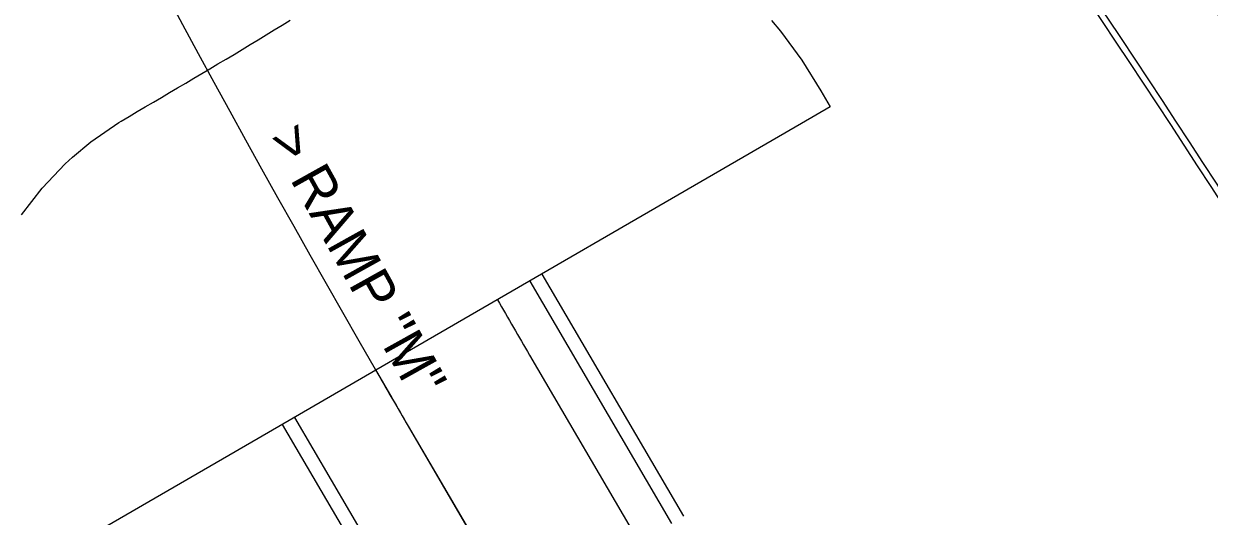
# Model space of a CAD drawing. Extents: x 2145147 to 2158018, y 137519 to 148068.
# Drawn here: x 2150446.2 to 2150572.7, y 142292.5 to 142345 of the extents above; entities that cross this region are included whole.
import ezdxf

# ---------------------------------------------------------------- set-up
doc = ezdxf.new("R2010")
doc.units = 0
for name, color, linetype in [('PR_Align_Ramp_M', 7, 'Continuous'), ('PR_Align_Ramp_M_Label', 7, 'Continuous'), ('PR_Phasing_Pavement_6', 7, 'Continuous')]:
    doc.layers.add(name, color=color, linetype=linetype)

msp = doc.modelspace()

# ---------------------------------------------------------------- linework, layer by layer
at = {"layer": 'PR_Align_Ramp_M'}
msp.add_line((2150487.2, 142302.12), (2150498.88, 142282.17), dxfattribs=at)
msp.add_line((2150487.2, 142302.12), (2150498.88, 142282.17), dxfattribs=at)
msp.add_arc((2151723.51, 143025.52), 1432.39, 201.35428, 210.33307, dxfattribs=at)
msp.add_arc((2151723.51, 143025.52), 1432.39, 201.35428, 210.33307, dxfattribs=at)
at = {"layer": 'PR_Phasing_Pavement_6'}
for p, q in [((2150475.07, 142303.06), (2150490.25, 142277.13)), ((2150473.77, 142302.31), (2150488.95, 142276.37)), ((2150487.21, 142302.12), (2150498.88, 142282.18))]:
    msp.add_line(p, q, dxfattribs=at)
for points in [[(2150445.95, 142324.63), (2150448.15, 142327.47), (2150450.62, 142330.07), (2150451.38, 142330.78), (2150453.35, 142332.43), (2150456.33, 142334.48), (2150456.58, 142334.62), (2150457.44, 142335.13), (2150458.3, 142335.64), (2150459.16, 142336.15), (2150460.02, 142336.66), (2150460.88, 142337.16), (2150461.74, 142337.67), (2150462.61, 142338.18), (2150463.47, 142338.69), (2150464.33, 142339.2), (2150465.19, 142339.71), (2150466.05, 142340.21), (2150466.91, 142340.72), (2150467.77, 142341.23), (2150468.63, 142341.74), (2150469.49, 142342.25), (2150470.34, 142342.78), (2150471.2, 142343.3), (2150472.05, 142343.82), (2150472.9, 142344.34), (2150473.76, 142344.86), (2150474.61, 142345.39)], [(2150525.96, 142345.35), (2150526.93, 142344.22), (2150529.2, 142341.12), (2150531.21, 142337.86), (2150531.72, 142337), (2150532.23, 142336.14), (2150529.17, 142334.36), (2150483.74, 142308.08), (2150471.19, 142300.81)], [(2150500.17, 142317.59), (2150515.28, 142291.77)], [(2150501.47, 142318.34), (2150516.57, 142292.53)], [(2150500.15, 142309.7), (2150511.83, 142289.75)], [(2150471.19, 142300.81), (2150446.11, 142286.3)]]:
    msp.add_lwpolyline(points, dxfattribs=at)
for centre, radius, start, end in [((2149618.97, 141712.09), 1173.92, 25.75878, 56.56435), ((2149618.97, 141712.09), 1169.92, 25.75878, 56.56435), ((2149618.97, 141712.09), 1145.92, 0.50149, 56.56435), ((2149618.97, 141712.09), 1135.92, 18.76767, 35.75878), ((2149618.97, 141712.09), 1135.25, 18.76767, 35.75878), ((2151723.51, 143025.52), 1417.39, 210.05759, 210.33307), ((2151723.51, 143025.52), 1432.39, 210.05759, 210.33307)]:
    msp.add_arc(centre, radius, start, end, dxfattribs=at)

# ---------------------------------------------------------------- texts
at = {"layer": 'PR_Align_Ramp_M_Label'}
msp.add_text('> RAMP "M"', height=4.3, rotation=299.0912, dxfattribs=at).set_placement((2150472.14, 142332.78))
msp.add_text('> RAMP "M"', height=4.3, rotation=299.0912, dxfattribs=at).set_placement((2150472.14, 142332.78))

doc.saveas('drawing.dxf')
